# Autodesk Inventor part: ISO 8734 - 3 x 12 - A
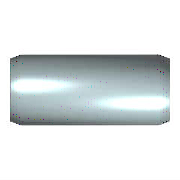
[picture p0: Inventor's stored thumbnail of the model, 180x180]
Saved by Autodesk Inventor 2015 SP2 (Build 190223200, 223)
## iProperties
IsCustomPart: 0
Created: 2012-02
Part Number: ISO 8734 - 3 x 12 - A
Material: Stahl
Description: Zylinderstift
Document SubType Name: Modeling
Standard: ISO 8734
Designer: rYan
Standards Organization: DIN
Language: de-DE
Size Designation: 3 x 12 - A
Categories: <MemberInstance><Categories><Category DisplayName="Verbindungselemente" InternalName="e4da775c-781d-43d5-af7c-5136215cf5a6" Mnemonic="FSTN"><Category DisplayNam
Density: 7.85 g/cm^3
Appearance: Platte
Author: rYan
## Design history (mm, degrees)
sketch "Skizze"
  geometry: C1 r 1.5 at (0, 0); 1 further point
  constraints: 1 centre point, 1 coincident
  dimensions: "d1" = 3 diameter of C1 (= NND)
extrude "Körper" new body sketch "Skizze" distance "d2" = 12 (= NLG); taper "d3" = 0 deg
body "Solid1"
chamfer "Fase1" distance "d4" = 0.5 (= PHH); stored, may be unused: angle "d5" = 15 deg (= FAWI), second distance "d11" = 0.5 (= PHH)
chamfer "Fase2" distance "d8" = 0.5 (= PHH); stored, may be unused: angle "d9" = 15 deg (= FAWI), second distance "d12" = 0.5 (= PHH)
other parameters: "NND" = 3 [user parameter; used in 1 equation term], "NLG" = 12 [user parameter; used in 1 equation term], "PHH" = 0.5 [user parameter; used in 5 equation terms], "FAWI" = 15 deg [user parameter; used in 2 equation terms], "d13" = 0, "d15" = 0, "d16" = 0, "PHH2" = 0.5 (= PHH) [user parameter], "FAWI2" = 15 deg [user parameter]
